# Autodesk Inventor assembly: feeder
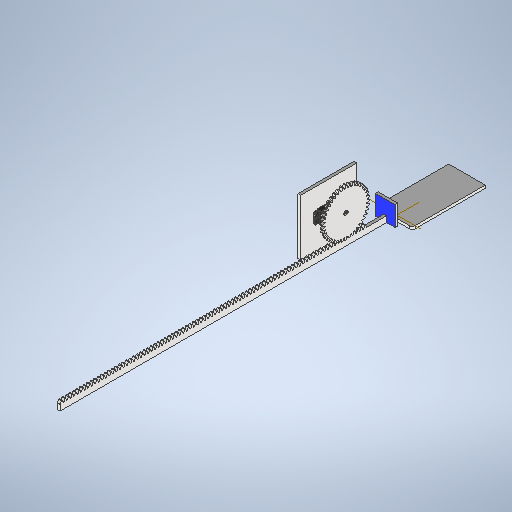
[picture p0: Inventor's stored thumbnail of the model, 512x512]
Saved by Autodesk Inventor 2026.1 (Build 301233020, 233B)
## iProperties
Created: 2026-10
Part Number: feeder
Document SubType Name: Assembly
Designer: alolo
Author: alolo
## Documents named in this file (7)
- C:\Users\hp\Documents\Inventor\DOM1_CartesianRobot\feeder.iam
- C:\Users\hp\Documents\Inventor\DOM1_CartesianRobot\pusher_pinion.ipt
- C:\Users\hp\Documents\Inventor\DOM1_CartesianRobot\Servo MG996R.ipt
- C:\Users\hp\Documents\Inventor\DOM1_CartesianRobot\pusher_base.ipt
- C:\Users\hp\Documents\Inventor\DOM1_CartesianRobot\pusher_support.ipt
- C:\Users\hp\Documents\Inventor\DOM1_CartesianRobot\pusher_punch.ipt
- C:\Users\hp\Documents\Inventor\DOM1_CartesianRobot\feeder_rack.ipt
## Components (6 placed, 6 different names)
1. Servo MG996R:1 — Angle:1, Mate:8, Mate:9, Mate:10, Rotational:1
2. pusher_base:1 — Mate:1, Mate:2, Mate:11, Mate:14, Mate:15, Slider:1
3. pusher_support — Mate:8, Mate:9, Mate:10, Mate:11
4. pusher_pinion:1 — Rotational:1, Flush:3, Rotation/Translation:1
5. pusher_punch:2 — Mate:14, Mate:16, Mate:17, Flush:4, Mate:34
6. feeder_rack:1
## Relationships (17: Mate 11, Flush 2, Angle 1, RevoluteJoint 1, TranslationJoint 1, RelateRotateTranslate 1)
- Mate:1: pusher_base:1
- Mate:2: pusher_base:1
- Angle:1: Servo MG996R:1
- Mate:8: Servo MG996R:1 ↔ pusher_support
- Mate:9: Servo MG996R:1 ↔ pusher_support
- Mate:10: Servo MG996R:1 ↔ pusher_support
- Rotational:1 [RevoluteJoint]: Servo MG996R:1 ↔ pusher_pinion:1
- Mate:11: pusher_base:1 ↔ pusher_support
- Mate:14: pusher_base:1 ↔ pusher_punch:2
- Mate:15: pusher_base:1
- Slider:1 [TranslationJoint]: pusher_base:1
- Flush:3: pusher_pinion:1
- Rotation/Translation:1 [RelateRotateTranslate]: pusher_pinion:1
- Mate:16: pusher_punch:2
- Mate:17: pusher_punch:2
- Flush:4: pusher_punch:2
- Mate:34: pusher_punch:2
